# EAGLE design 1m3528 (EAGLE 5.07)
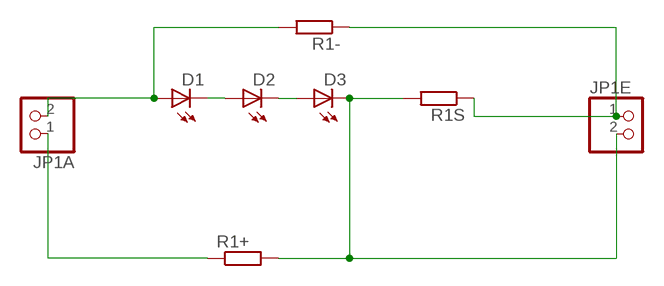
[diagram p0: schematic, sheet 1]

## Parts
D1  LED1210  [1210]
D2  LED1210  [1210]
D3  LED1210  [1210]
JP1A  PINHD-1X2  [1X02X05]
JP1E  PINHD-1X2  [1X02X05]
R1+  R-EU_R0603  [R0603]
R1-  R-EU_R0603  [R0603]
R1S  R-EU_R0603  [R0603]

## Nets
D1D2: D1.P$2(C) D2.P$1(A)
D2D3: D2.P$2(C) D3.P$1(A)
N$1: D1.P$1(A) JP1A.2 R1-.2
N$3: D3.P$2(C) JP1E.2 R1+.2 R1S.2
N$5: JP1A.1 R1+.1
N$25: JP1E.1 R1-.1 R1S.1

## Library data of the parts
D1-D3 = led(2):LED: LED
JP1A JP1E = pinhead:PINHD-1X2: PIN HEADER
R1+ R1- R1S = rcl:R-EU_: RESISTOR, European symbol

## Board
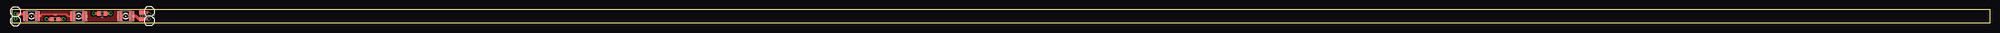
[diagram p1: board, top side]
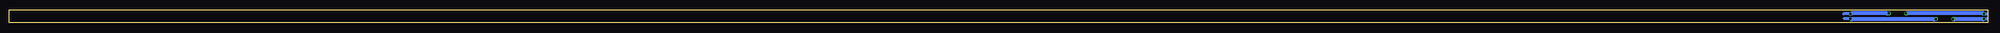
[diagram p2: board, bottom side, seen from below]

Size 525 x 3.5 mm. Coordinates in mm from the lower left corner, seen from the top.
Outline: 0,0 525,0 525,3.5 0,3.5 0,0
Copper layers (1*16): Top 0.035mm / dielectric 1.5mm / Bottom 0.035mm
Design rules "default *": minimum track width 10mil, minimum drill 10mil, track to track 8mil, track to pad 8mil, pad to pad 8mil, via to via 8mil, smd to smd 8mil, copper to edge 10mil, drill to drill 8mil, minimum pad ring 5mil, minimum via ring 8mil, stop-mask expansion 0.0025mm, vias tented up to drill 0mil, thermal gap 10mil

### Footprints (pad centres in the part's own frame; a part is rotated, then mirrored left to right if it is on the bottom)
1210 = smd 1.27 x 2.54: P$1 1.587,0; P$2 -1.587,0
1X02X05 = drill 0.5 pad 0.813 round: 1 -0.635,0; 2 0.635,0
R0603 = smd 1 x 1.1: 1 -0.85,0; 2 0.85,0

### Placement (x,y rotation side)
D1  5.25,1.75 180 top
D2  17.75,1.75 180 top
D3  30.25,1.75 180 top
JP1A  1,1.75 90 top
JP1E  36.5,1.75 270 top
R1+  11.5,1 0 top
R1-  24,2.5 180 top
R1S  34.4,1.8 270 top

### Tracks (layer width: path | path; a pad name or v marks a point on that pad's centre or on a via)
D1D2
  Top 0.406: D1.P$2 7.5,1.75 8,2.25 14.5,2.25 15,1.75 D2.P$1
  pour Top (isolate 0.406): 6.75,3 16,3 16,0.5 6.75,0.5 6.75,0.75
D2D3
  pour Top (isolate 0.406): 19.25,3 28.5,3 28.5,0.5 19.25,0.5 19.25,0.75
N$1  (via drill 0.5 pad 0.61)
  Top 0.406: 3.03,2.38 D1.P$1
  Top 0.813: JP1A.2 3.03,2.38 | v21.75,2.5 R1-.2
  Bottom 0.406: JP1A.2 1.11,2.5 1.11,2.62 1.25,2.55 | 21.5,2.55 v21.75,2.5
  Bottom 1.016: 1.25,2.55 21.5,2.55
N$2
  Bottom 0.813: 36.7,2.4 38.25,2.4
N$3  (via drill 0.5 pad 0.61)
  Top 0.406: 33.75,1 34.35,1 R1S.2 | JP1E.2 36.34,0.95
  Top 0.813: R1+.2 v13.75,1 | D3.P$2 33,1.75 33.75,1 | 36.34,0.95 R1S.2
  Bottom 0.406: 36.38,1 JP1E.2 36.13,0.95 | v13.75,1 14,1 14.25,0.95
  Bottom 1.016: 14.25,0.95 36.13,0.95
N$4
  Bottom 0.813: 36.5,1.1 38.15,1.1
N$5  (via drill 0.5 pad 0.61)
  Top 0.813: v9.25,1 R1+.1
  Bottom 0.406: 9.13,1.11 v9.25,1 9,0.95 | JP1A.1 1,1 1.25,0.95
  Bottom 1.016: 1.25,0.95 9,0.95
N$6
  Bottom 0.813: 0.9,1.1 0.2,1.1
N$7
  Bottom 0.813: 1,2.4 0.2,2.4
N$25  (via drill 0.5 pad 0.61)
  Top 0.406: JP1E.1 36.23,2.65
  Top 0.813: R1-.1 v26.25,2.5 | 36.23,2.65 R1S.1
  Bottom 0.406: 36.38,2.5 JP1E.1 36.13,2.55 | v26.25,2.5 26.5,2.5 26.75,2.55
  Bottom 1.016: 26.75,2.55 36.13,2.55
